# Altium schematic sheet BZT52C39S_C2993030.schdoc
size 127 x 101 mm
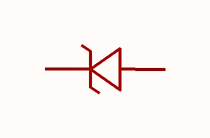
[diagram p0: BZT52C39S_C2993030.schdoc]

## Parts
D?  bzt52c39s_c2993030  [SOD-323_L1.8-W1.3-LS2.5-RD]  (value not drawn)

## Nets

Not connected (* = marked no-connect by the designer): D? 1(K) 2(A)

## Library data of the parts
D? = bzt52c39s_c2993030: 二极管配置:1个独立式;稳压值(标称值):39V;稳压值(范围值):37V~41V;耗散功率(Pd):200mW;; Manufacturer: MDD(辰达半导体); AddInBom: yes; ModelId: db63db13d9e342eb939127d413d6200b; ModelTransform: 104.3305,51.181,0,0,0,0,0,-0.004,0; Diode Configuration: 1个独立式; Zener Voltage(Nom): 39V; Reverse Leakage Current (Ir): 100nA@30V; Pd - Power Dissipation: 200mW; Impedance(Zzt): 100Ω; Tolerance: ±5%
